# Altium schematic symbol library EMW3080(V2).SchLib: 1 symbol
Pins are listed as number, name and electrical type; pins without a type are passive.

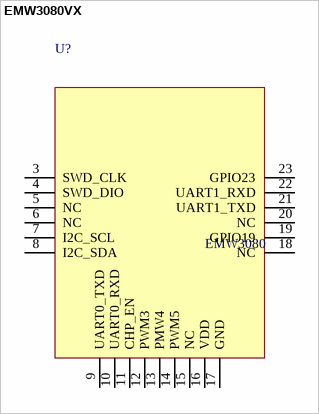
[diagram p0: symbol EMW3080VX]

## EMW3080VX
designator U?, comment EMW3080
footprint EMW3071 (Footprint of EMW3071)
pins: 3 SWD_CLK, 4 SWD_DIO, 5 NC, 6 NC, 7 I2C_SCL, 8 I2C_SDA, 9 UART0_TXD, 10 UART0_RXD, 11 CHP_EN, 12 PWM3, 13 PMW4, 14 PWM5, 15 NC, 16 VDD, 17 GND, 18 NC, 19 GPIO19, 20 NC, 21 UART1_TXD, 22 UART1_RXD, 23 GPIO23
